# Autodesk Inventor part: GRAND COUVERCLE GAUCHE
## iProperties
Created: 2004-11
Part Number: GRAND COUVERCLE GAUCHE
Document SubType Name: Modeling
Designer: Bruno
Manufacturer: Standard
Standards Organization: Custom
Author: Bruno
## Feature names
1. Base1
